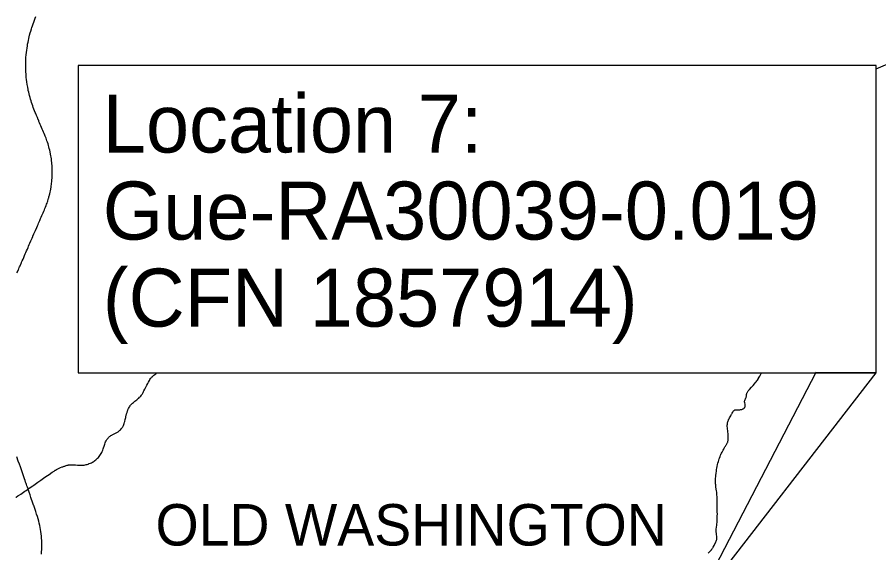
# Model space of a CAD drawing. Extents: x 1761803 to 2441803, y 509895 to 949895.
# Drawn here: x 2230200 to 2271766, y 839765 to 865604 of the extents above; entities that cross this region are included whole.
import ezdxf

# ---------------------------------------------------------------- set-up
doc = ezdxf.new("R2010")
doc.units = 0
for name, color, linetype in [('Default', 7, 'Continuous'), ('GM_X_County_Road', 7, 'Continuous'), ('GM_X_Minor_Lake', 7, 'Continuous'), ('GM_X_Minor_River', 7, 'Continuous'), ('GM_X_Minor_River_Text', 7, 'Continuous'), ('GM_X_State_Location', 7, 'Continuous')]:
    doc.layers.add(name, color=color, linetype=linetype)

msp = doc.modelspace()

# ---------------------------------------------------------------- linework, layer by layer
at = {"layer": 'Default'}
msp.add_lwpolyline([(2233137, 848451), (2271645, 848451), (2271645, 863275), (2233137, 863275)], close=True, dxfattribs=at)
at = {"layer": 'GM_X_Minor_Lake'}
for points in [[(2264076, 844324), (2264080, 844335), (2264109, 844411), (2264133, 844469), (2264150, 844508), (2264169, 844550), (2264183, 844576), (2264206, 844620), (2264259, 844714), (2264287, 844766), (2264315, 844814), (2264346, 844868), (2264370, 844908), (2264407, 844973), (2264417, 844990), (2264433, 845019), (2264451, 845053), (2264465, 845082), (2264477, 845109), (2264483, 845127), (2264489, 845149), (2264495, 845181), (2264500, 845223), (2264504, 845281), (2264506, 845333), (2264505, 845389), (2264502, 845438), (2264498, 845490), (2264484, 845614), (2264479, 845653), (2264468, 845737), (2264461, 845799), (2264457, 845852), (2264457, 845885), (2264458, 845928), (2264461, 845967), (2264466, 846003), (2264474, 846042), (2264484, 846080), (2264497, 846125), (2264509, 846159), (2264522, 846189), (2264541, 846228), (2264570, 846279), (2264622, 846366), (2264649, 846415), (2264667, 846446), (2264680, 846469), (2264698, 846500), (2264723, 846546), (2264742, 846581), (2264759, 846605), (2264774, 846624), (2264785, 846635), (2264799, 846646), (2264811, 846653), (2264824, 846658), (2264843, 846663), (2264867, 846665), (2264900, 846667), (2264949, 846667), (2264982, 846667), (2265021, 846667), (2265056, 846669), (2265099, 846672), (2265134, 846677), (2265162, 846683), (2265190, 846691), (2265214, 846702), (2265231, 846711), (2265249, 846724), (2265266, 846738), (2265281, 846755), (2265294, 846773), (2265304, 846789), (2265313, 846810), (2265320, 846831), (2265325, 846853), (2265327, 846875), (2265327, 846898), (2265326, 846904), (2265323, 846920), (2265318, 846942), (2265300, 847002), (2265297, 847016), (2265294, 847037), (2265294, 847057), (2265296, 847084), (2265302, 847115), (2265314, 847152), (2265330, 847190), (2265354, 847238), (2265367, 847264), (2265376, 847292), (2265382, 847315), (2265387, 847351), (2265391, 847386), (2265392, 847413), (2265395, 847435), (2265401, 847460), (2265413, 847490), (2265429, 847519), (2265447, 847549), (2265472, 847584), (2265527, 847649), (2265624, 847760), (2265701, 847843), (2265763, 847909), (2265821, 847972), (2265853, 848010), (2265886, 848054), (2265916, 848099), (2265956, 848168), (2265967, 848186), (2266030, 848292), (2266097, 848412), (2266118, 848451)], [(2263839, 840153), (2263908, 840288), (2263927, 840331), (2263940, 840369), (2263948, 840402), (2263952, 840429), (2263956, 840463), (2263957, 840493), (2263956, 840527), (2263951, 840573), (2263941, 840636), (2263931, 840704), (2263924, 840747), (2263921, 840783), (2263920, 840816), (2263921, 840852), (2263925, 840904), (2263938, 841008), (2263948, 841090), (2263956, 841165), (2263964, 841230), (2263968, 841279), (2263974, 841406), (2263977, 841524), (2263978, 841636), (2263977, 841718), (2263977, 841816), (2263975, 841931), (2263974, 841990), (2263973, 842088), (2263973, 842104), (2263972, 842196), (2263969, 842324), (2263965, 842432), (2263954, 842589), (2263946, 842681), (2263938, 842752), (2263928, 842827), (2263910, 842947), (2263898, 843041), (2263893, 843087), (2263891, 843120), (2263890, 843153), (2263891, 843225), (2263892, 843311), (2263895, 843360), (2263900, 843425), (2263905, 843487), (2263917, 843598), (2263931, 843709), (2263942, 843781), (2263953, 843852), (2263967, 843920), (2263991, 844022), (2264009, 844092), (2264028, 844165), (2264046, 844228), (2264069, 844304), (2264076, 844324)], [(2263532, 839743), (2263553, 839769), (2263567, 839783), (2263579, 839794), (2263595, 839810), (2263639, 839849), (2263657, 839868), (2263678, 839892), (2263692, 839910), (2263702, 839923), (2263718, 839944), (2263729, 839959), (2263745, 839984), (2263756, 840000), (2263780, 840043), (2263818, 840112), (2263839, 840153)]]:
    msp.add_lwpolyline(points, dxfattribs=at)
at = {"layer": 'GM_X_Minor_River'}
for points in [[(2230189, 853275), (2230208, 853320), (2230260, 853440), (2230273, 853470), (2230298, 853524), (2230315, 853563), (2230335, 853608), (2230370, 853689), (2230386, 853725), (2230408, 853776), (2230414, 853788), (2230443, 853857), (2230479, 853938), (2230514, 854019), (2230550, 854100), (2230585, 854182), (2230614, 854248), (2230652, 854335), (2230689, 854419), (2230723, 854497), (2230750, 854560), (2230783, 854635), (2230815, 854708), (2230863, 854819), (2230919, 854948), (2230952, 855023), (2230960, 855041), (2231009, 855156), (2231081, 855321), (2231140, 855457), (2231176, 855538), (2231205, 855607), (2231230, 855664), (2231246, 855700), (2231286, 855794), (2231329, 855890), (2231358, 855959), (2231391, 856031), (2231420, 856100), (2231451, 856169), (2231482, 856241), (2231513, 856314), (2231539, 856377), (2231568, 856447), (2231595, 856517), (2231620, 856582), (2231641, 856640), (2231659, 856693), (2231672, 856734), (2231676, 856746), (2231695, 856806), (2231714, 856872), (2231718, 856885), (2231733, 856938), (2231746, 856986), (2231754, 857021), (2231757, 857030), (2231770, 857081), (2231787, 857158), (2231803, 857235), (2231818, 857313), (2231819, 857317), (2231832, 857397), (2231843, 857461), (2231852, 857533), (2231858, 857575), (2231870, 857683), (2231876, 857758), (2231883, 857840), (2231887, 857919), (2231891, 857994), (2231892, 858066), (2231892, 858148), (2231890, 858224), (2231889, 858296), (2231885, 858378), (2231881, 858450), (2231875, 858529), (2231868, 858601), (2231860, 858676), (2231848, 858767), (2231836, 858848), (2231826, 858909), (2231824, 858922), (2231808, 859003), (2231788, 859103), (2231767, 859195), (2231748, 859272), (2231728, 859345), (2231710, 859408), (2231685, 859490), (2231660, 859568), (2231636, 859639), (2231612, 859707), (2231590, 859766), (2231552, 859863), (2231528, 859921), (2231498, 859994), (2231468, 860063), (2231438, 860135), (2231407, 860208), (2231375, 860284), (2231345, 860356), (2231311, 860434), (2231282, 860504), (2231250, 860579), (2231240, 860603), (2231222, 860649), (2231218, 860658), (2231191, 860721), (2231175, 860761), (2231160, 860797), (2231158, 860803), (2231156, 860806), (2231131, 860867), (2231111, 860915), (2231100, 860942), (2231096, 860951), (2231069, 861015), (2231039, 861088), (2231007, 861166), (2230977, 861243), (2230946, 861329), (2230920, 861407), (2230893, 861488), (2230868, 861569), (2230842, 861653), (2230818, 861735), (2230795, 861821), (2230774, 861903), (2230754, 861986), (2230736, 862069), (2230725, 862124), (2230704, 862234), (2230683, 862353), (2230665, 862480), (2230650, 862600), (2230639, 862698), (2230632, 862782), (2230625, 862867), (2230619, 862956), (2230615, 863021), (2230610, 863139), (2230609, 863234), (2230609, 863319), (2230611, 863411), (2230615, 863519), (2230623, 863660), (2230632, 863784), (2230643, 863895), (2230658, 864019), (2230673, 864119), (2230689, 864216), (2230703, 864300), (2230721, 864397), (2230740, 864487), (2230759, 864577), (2230776, 864650), (2230799, 864745), (2230828, 864856), (2230850, 864932), (2230886, 865044), (2230910, 865116), (2230934, 865187), (2230969, 865286), (2230999, 865373), (2231030, 865463), (2231063, 865556), (2231093, 865639)], [(2231364, 839697), (2231374, 839805), (2231381, 839916), (2231385, 840034), (2231387, 840143), (2231385, 840251), (2231381, 840363), (2231375, 840471), (2231366, 840572), (2231355, 840677), (2231341, 840784), (2231325, 840888), (2231307, 840985), (2231287, 841084), (2231263, 841190), (2231237, 841292), (2231210, 841398), (2231176, 841507), (2231137, 841632), (2231097, 841750), (2230995, 842040), (2230987, 842063), (2230956, 842156), (2230863, 842436), (2230820, 842560), (2230775, 842689), (2230742, 842786), (2230722, 842842), (2230692, 842925), (2230679, 842962), (2230667, 842996), (2230647, 843055), (2230627, 843114), (2230607, 843170), (2230577, 843257), (2230554, 843325), (2230536, 843374), (2230487, 843517), (2230451, 843619), (2230384, 843814), (2230353, 843904), (2230303, 844047), (2230252, 844192), (2230183, 844394)]]:
    msp.add_lwpolyline(points, dxfattribs=at)
at = {"layer": 'GM_X_Minor_River_Text'}
for points in [[(2271645, 863120), (2272504, 863479), (2272665, 863545), (2272864, 863629), (2272970, 863675), (2273205, 863774), (2273381, 863847), (2273495, 863896), (2273649, 863961), (2273828, 864033), (2273911, 864064), (2274036, 864107), (2274055, 864114), (2274166, 864150), (2274290, 864188), (2274363, 864209)], [(2233635, 844048), (2233679, 844064), (2233730, 844086), (2233780, 844109), (2233824, 844132), (2233869, 844158), (2233912, 844187), (2233949, 844214), (2233993, 844248), (2234039, 844289), (2234079, 844328), (2234118, 844368), (2234156, 844412), (2234191, 844456), (2234223, 844505), (2234256, 844558), (2234280, 844604), (2234303, 844651), (2234329, 844714), (2234354, 844782), (2234369, 844828), (2234395, 844909), (2234427, 845010), (2234447, 845066), (2234466, 845114), (2234487, 845159), (2234508, 845197), (2234531, 845233), (2234555, 845265), (2234580, 845296), (2234609, 845327), (2234638, 845355), (2234660, 845374), (2234689, 845396), (2234724, 845421), (2234757, 845442), (2234786, 845458), (2234853, 845494), (2234978, 845557), (2235033, 845587), (2235066, 845607), (2235104, 845633), (2235135, 845656), (2235163, 845679), (2235188, 845704), (2235218, 845738), (2235244, 845772), (2235270, 845809), (2235295, 845848), (2235312, 845879), (2235327, 845911), (2235343, 845951), (2235360, 846000), (2235378, 846060), (2235388, 846101), (2235411, 846190), (2235434, 846286), (2235444, 846327), (2235480, 846467), (2235497, 846534), (2235520, 846609), (2235535, 846653), (2235540, 846665), (2235548, 846686), (2235570, 846731), (2235595, 846774), (2235619, 846813), (2235646, 846851), (2235672, 846884), (2235698, 846914), (2235725, 846943), (2235758, 846975), (2235808, 847019), (2235874, 847073), (2235966, 847146), (2236033, 847200), (2236070, 847232), (2236106, 847265), (2236128, 847289), (2236158, 847323), (2236188, 847362), (2236216, 847402), (2236240, 847441), (2236274, 847504), (2236294, 847542), (2236312, 847577), (2236353, 847655), (2236409, 847759), (2236441, 847822), (2236458, 847855), (2236499, 847934), (2236536, 848004), (2236574, 848072), (2236604, 848120), (2236637, 848169), (2236664, 848207), (2236685, 848232), (2236721, 848270), (2236755, 848302), (2236797, 848339), (2236838, 848371), (2236881, 848402), (2236920, 848427), (2236954, 848446)], [(2232045, 843750), (2232095, 843778), (2232159, 843812), (2232218, 843841), (2232293, 843875), (2232369, 843906), (2232402, 843919)], [(2232402, 843919), (2232431, 843930), (2232457, 843938)], [(2232457, 843938), (2232493, 843951), (2232559, 843971), (2232607, 843984), (2232664, 843997), (2232680, 844000), (2232703, 844004), (2232739, 844008), (2232785, 844010), (2232845, 844010), (2232923, 844007), (2232992, 844002), (2233004, 844001), (2233116, 843992), (2233210, 843986), (2233279, 843985), (2233331, 843987), (2233383, 843991), (2233431, 843998), (2233482, 844007), (2233530, 844017), (2233580, 844031), (2233633, 844047), (2233635, 844048)], [(2230625, 842776), (2230692, 842822), (2230722, 842842), (2230774, 842878), (2230953, 843001), (2231000, 843034), (2231061, 843076), (2231187, 843164), (2231333, 843265), (2231472, 843361), (2231587, 843440), (2231735, 843543), (2231892, 843650), (2231979, 843709), (2232035, 843744), (2232045, 843750)], [(2230133, 842428), (2230157, 842446), (2230236, 842504), (2230244, 842510), (2230264, 842524), (2230370, 842599), (2230564, 842733), (2230625, 842776)]]:
    msp.add_lwpolyline(points, dxfattribs=at)
at = {"layer": 'GM_X_State_Location'}
msp.add_lwpolyline([(2262773, 836988), (2271645, 848451), (2268723, 848457)], close=True, dxfattribs=at)

# ---------------------------------------------------------------- texts
at = {"layer": 'GM_X_County_Road'}
msp.add_text('OLD WASHINGTON', height=2000, rotation=0, dxfattribs=at).set_placement((2236873, 840114))
at = {"layer": 'GM_X_State_Location'}
for s, p in [('Location 7:', (2234328, 859075)), ('Gue-RA30039-0.019', (2234328, 854875)), ('(CFN 1857914)', (2234328, 850675))]:
    msp.add_text(s, height=2800, dxfattribs=at).set_placement(p)

doc.saveas('drawing.dxf')
